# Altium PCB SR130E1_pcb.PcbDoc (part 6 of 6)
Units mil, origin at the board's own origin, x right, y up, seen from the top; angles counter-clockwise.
Board outline 5700 x 4800 mil, 6 copper layers (Top Layer, Signal Layer 1, Signal Layer 2, Signal Layer 3, Signal Layer 4, Bottom Layer), stack 61.4 mil thick; 452 components, 288 nets, 1391 pads, 911 vias.
Unrouted connection lines stored in the file: 523.
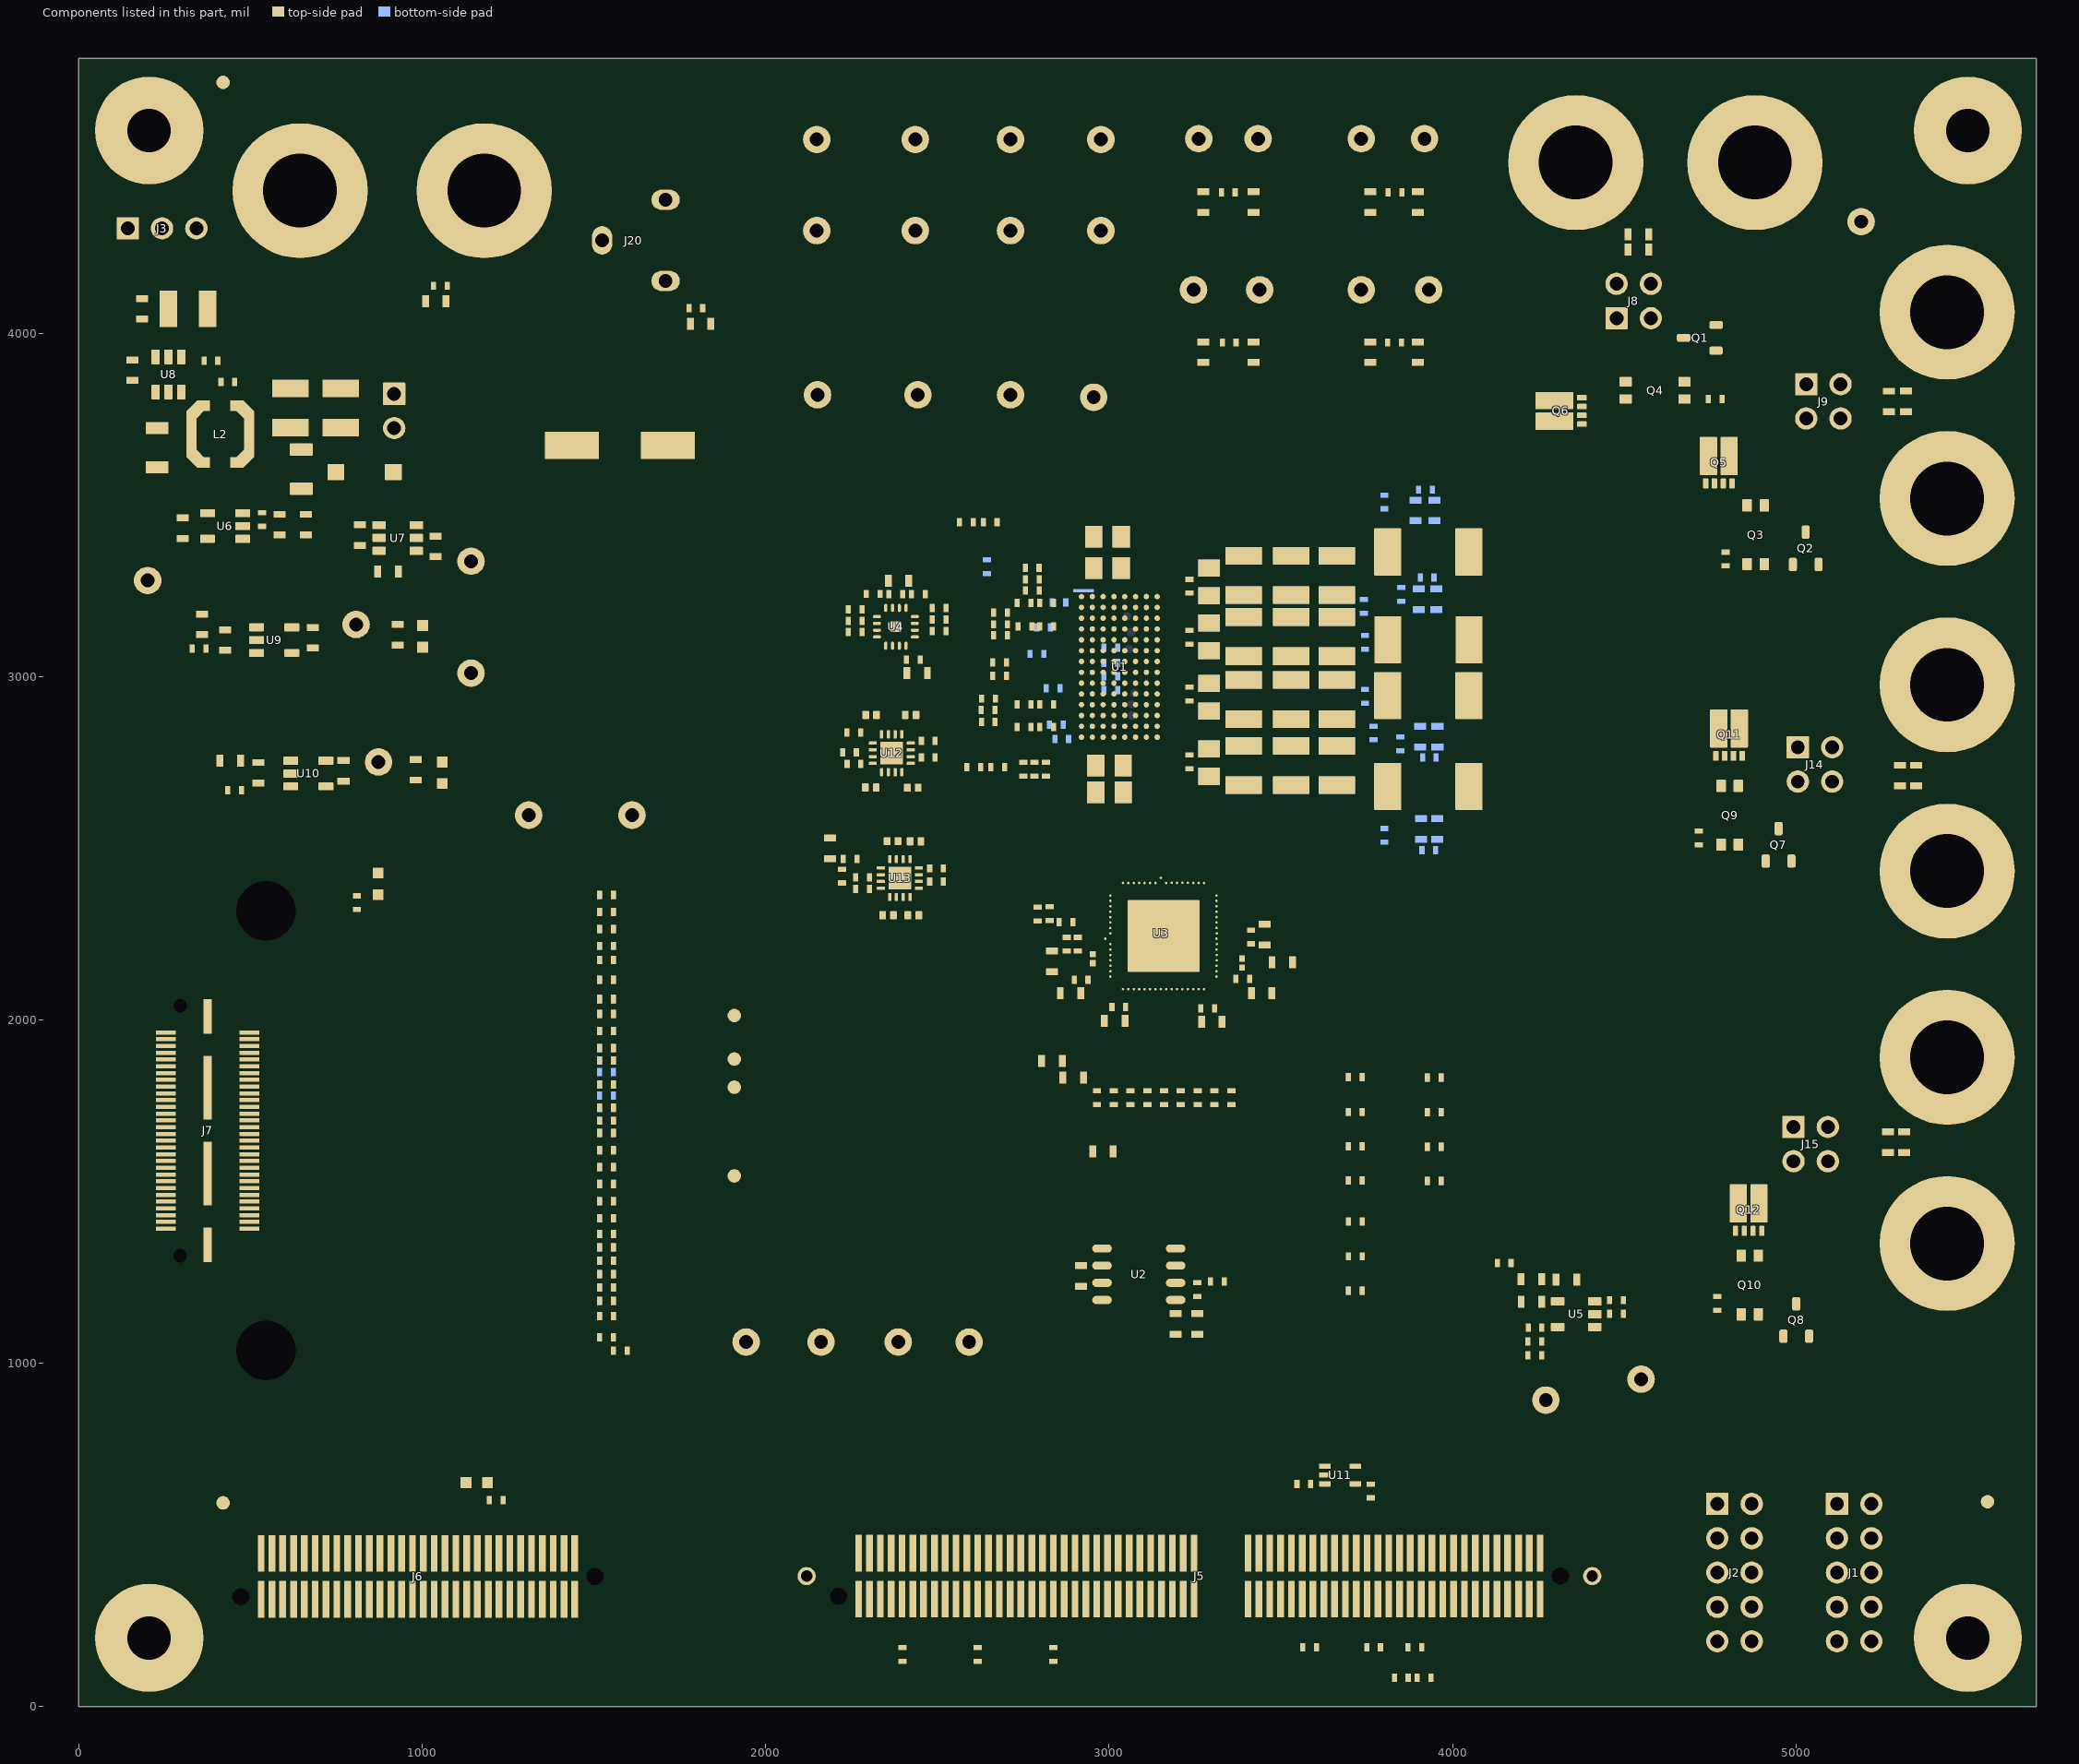
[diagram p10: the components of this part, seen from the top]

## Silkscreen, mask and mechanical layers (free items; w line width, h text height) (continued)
Drill Drawing:
  circle w10: c6482.56,3703.87 r27.63
  lines w10: 6454.93,3178.96 6454.93,3192.77 6468.75,3206.59 6454.93,3220.4 6454.93,3234.21 6468.75,3234.21 6482.56,3220.4 6496.37,3234.21 6510.19,3234.21 6510.19,3220.4 6496.37,3206.59 6510.19,3192.77 6510.19,3178.96 6496.37,3178.96 6482.56,3192.77 6468.75,3178.96 6454.93,3178.96 ; 6454.93,3317.09 6468.75,3317.09 6482.56,3303.28 6496.37,3317.09 6510.19,3317.09 6496.37,3330.91 6510.19,3344.72 6496.37,3344.72 6482.56,3358.53 6468.75,3344.72 6454.93,3344.72 6468.75,3330.91 6454.93,3317.09 ; 6454.93,3455.23 6482.56,3427.6 6510.19,3455.23 6482.56,3482.85 6454.93,3455.23 ; 6454.93,3551.92 6510.19,3551.92 6510.19,3607.17 6454.93,3607.17 6454.93,3551.92 ; 6454.93,3855.81 6510.19,3855.81 6482.56,3800.56 6454.93,3855.81 ; 6454.93,3980.13 6510.19,3980.13 6482.56,3924.88 6454.93,3980.13 ; 6454.93,4049.2 6510.19,4049.2 6510.19,4104.45 6454.93,4104.45 6454.93,4049.2 ; 6454.93,4187.33 6468.75,4187.33 6468.75,4173.52 6496.37,4173.52 6496.37,4187.33 6510.19,4187.33 6510.19,4214.96 6496.37,4214.96 6496.37,4228.77 6468.75,4228.77 6468.75,4214.96 6454.93,4214.96 6454.93,4187.33 ; 6454.93,4297.84 6454.93,4311.65 6468.75,4325.47 6454.93,4339.28 6454.93,4353.09 6468.75,4353.09 6482.56,4339.28 6496.37,4353.09 6510.19,4353.09 6510.19,4339.28 6496.37,4325.47 6510.19,4311.65 6510.19,4297.84 6496.37,4297.84 6482.56,4311.65 6468.75,4297.84 6454.93,4297.84 ; 6454.93,4422.16 6482.56,4435.97 6510.19,4422.16 6496.37,4449.79 6510.19,4477.41 6482.56,4463.6 6454.93,4477.41 6468.75,4449.79 6454.93,4422.16 ; 6465.98,3190.01 6465.98,3198.3 6474.27,3206.59 6465.98,3214.87 6465.98,3223.16 6474.27,3223.16 6482.56,3214.87 6490.85,3223.16 6499.14,3223.16 6499.14,3214.87 6490.85,3206.59 6499.14,3198.3 6499.14,3190.01 6490.85,3190.01 6482.56,3198.3 6474.27,3190.01 6465.98,3190.01 ; 6465.98,3562.97 6499.14,3562.97 6499.14,3596.12 6465.98,3596.12 6465.98,3562.97 ; 6465.98,3844.76 6499.14,3844.76 6482.56,3811.61 6465.98,3844.76
  lines w12: 6404.84,3141.66 9589.84,3141.66 ; 6404.84,4509.18 9589.84,4509.18 ; 6742.7,3017.34 6742.7,4633.5 ; 7071.99,3017.34 7071.99,4633.5 ; 7664.78,3017.34 7664.78,4633.5 ; 7923.92,3017.34 7923.92,4633.5 ; 8299.08,3017.34 8299.08,4633.5 ; 9023.41,3017.34 9023.41,4633.5 ; 6404.84,3017.34 9589.84,3017.34 9589.84,4633.5 6404.84,4633.5 6404.84,3017.34
  text "Symbol" at 6479.43,4546.48 h72
  text "Count" at 6780,4546.48 h72
  text "Hole Size" at 7109.28,4546.48 h72
  text "Plated" at 7702.08,4546.48 h72
  text "Hole Type" at 7961.22,4546.48 h72
  text "Drill Layer Pair" at 8336.38,4546.48 h72
  text "Hole Tolerance" at 9060.71,4546.48 h72
  text "442" at 6780,4422.16 h60
  text "8.00mil (0.203mm)" at 7109.28,4422.16 h60
  text "PTH" at 7702.08,4422.16 h60
  text "Round" at 7961.22,4422.16 h60
  text "Top Layer - Bottom Layer" at 8336.38,4422.16 h60
  text "34" at 6780,4297.84 h60
  text "8.00mil (0.203mm)" at 7109.28,4297.84 h60
  text "PTH" at 7702.08,4297.84 h60
  text "Round" at 7961.22,4297.84 h60
  text "Top Layer - Bottom Layer" at 8336.38,4297.84 h60
  text "435" at 6780,4173.52 h60
  text "10.00mil (0.254mm)" at 7109.28,4173.52 h60
  text "PTH" at 7702.08,4173.52 h60
  text "Round" at 7961.22,4173.52 h60
  text "Top Layer - Bottom Layer" at 8336.38,4173.52 h60
  text "2" at 6780,4049.2 h60
  text "33.07mil (0.840mm)" at 7109.28,4049.2 h60
  text "PTH" at 7702.08,4049.2 h60
  text "Round" at 7961.22,4049.2 h60
  text "Top Layer - Bottom Layer" at 8336.38,4049.2 h60
  text "3" at 6780,3924.88 h60
  text "39.37mil (1.000mm)" at 7109.28,3924.88 h60
  text "PTH" at 7702.08,3924.88 h60
  text "Slot" at 7961.22,3924.88 h60
  text "Top Layer - Bottom Layer" at 8336.38,3924.88 h60
  text "2" at 6780,3800.56 h60
  text "40.00mil (1.016mm)" at 7109.28,3800.56 h60
  text "NPTH" at 7702.08,3800.56 h60
  text "Round" at 7961.22,3800.56 h60
  text "Top Layer - Bottom Layer" at 8336.38,3800.56 h60
  text "75" at 6780,3676.24 h60
  text "40.00mil (1.016mm)" at 7109.28,3676.24 h60
  text "PTH" at 7702.08,3676.24 h60
  text "Round" at 7961.22,3676.24 h60
  text "Top Layer - Bottom Layer" at 8336.38,3676.24 h60
  text "4" at 6780,3551.92 h60
  text "50.00mil (1.270mm)" at 7109.28,3551.92 h60
  text "NPTH" at 7702.08,3551.92 h60
  text "Round" at 7961.22,3551.92 h60
  text "Top Layer - Bottom Layer" at 8336.38,3551.92 h60
  text "4" at 6780,3427.6 h60
  text "125.98mil (3.200mm)" at 7109.28,3427.6 h60
  text "PTH" at 7702.08,3427.6 h60
  text "Round" at 7961.22,3427.6 h60
  text "Top Layer - Bottom Layer" at 8336.38,3427.6 h60
  text "2" at 6780,3303.28 h60
  text "173.23mil (4.400mm)" at 7109.28,3303.28 h60
  text "NPTH" at 7702.08,3303.28 h60
  text "Round" at 7961.22,3303.28 h60
  text "Top Layer - Bottom Layer" at 8336.38,3303.28 h60
  text "10" at 6780,3178.96 h60
  text "214.57mil (5.450mm)" at 7109.28,3178.96 h60
  text "PTH" at 7702.08,3178.96 h60
  text "Round" at 7961.22,3178.96 h60
  text "Top Layer - Bottom Layer" at 8336.38,3178.96 h60
  text "1013 Total" at 6780,3054.64 h60
  text "Slot definitions :" at 6479.43,2967.62 h60
  text "Routed Path Length" at 6930.15,2967.62 h60
  text "= Calculated from tool start centre position to tool end centre position." at 7469.89,2967.62 h60
  text "Hole Length" at 6930.15,2917.89 h60
  text "= Routed Path Length + Tool Size = Slot length as defined in the PCB layout" at 7270.09,2917.89 h60
  text ".Layer_Name" at 579,-1694.49 h60
M17 Embedded Cavity:
  text ".Layer_Name" at 579,-1694.49 h60
M18 Embedded Assembly:
  text ".Layer_Name" at 579,-1694.49 h60
M19 Embedded Keepout:
  text ".Layer_Name" at 579,-1694.49 h60

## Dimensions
0,4800 to 5700,0 on M2 Board Dimensions
2,-1236 to 1002,-1236 on M2 Board Dimensions
0,0 to 0,4800 on M2 Board Dimensions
